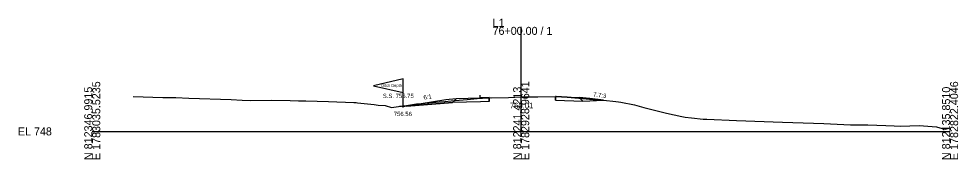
# Model space of a CAD drawing. Extents: x 5574 to 10203, y -10 to 9546.
# Drawn here: x 8574.3 to 8902.8, y 3990.3 to 4039.3 of the extents above; entities that cross this region are included whole.
import ezdxf

# ---------------------------------------------------------------- set-up
doc = ezdxf.new("R2010")
doc.units = 0
for name, color, linetype in [('Exist Cross Section Cell', 7, 'Continuous'), ('Exist XS Center Line Elevation Label', 7, 'Continuous'), ('Exist XS Ground Line', 7, 'Continuous'), ('Prop XS Ditch Slope Text', 7, 'Continuous'), ('Prop XS Ditch Standard Text', 7, 'Continuous'), ('Prop XS Dump Level', 7, 'Continuous'), ('Prop XS Earthwork Shape', 7, 'Continuous'), ('Prop XS EOT Tick Mark', 7, 'Continuous'), ('Prop XS Finish Grade', 7, 'Continuous'), ('Prop XS Finish Grade Earthwork', 7, 'Continuous'), ('Prop XS Finish Grade Paved Shoulder', 7, 'Continuous'), ('Prop XS Finish Grade Pavement', 7, 'Continuous'), ('Prop XS Hydro Typical Ditch Data', 7, 'Continuous'), ('Prop XS Pvmt Edge Slope', 7, 'Continuous'), ('Prop XS SS Elevation Text', 7, 'Continuous'), ('Prop XS Subgrade Earthwork', 7, 'Continuous'), ('Scratch_Level_3', 7, 'Continuous'), ('Scratch_Level_6', 7, 'Continuous')]:
    doc.layers.add(name, color=color, linetype=linetype)

msp = doc.modelspace()

# ---------------------------------------------------------------- linework, layer by layer
at = {"layer": 'Exist Cross Section Cell'}
for p, q in [((8750, 4000), (8750, 4036.49)), ((8600, 4000), (8750, 4000)), ((8750, 4000), (8900, 4000))]:
    msp.add_line(p, q, dxfattribs=at)
at = {"layer": 'Exist XS Ground Line'}
for p, q in [((8614.31, 4012.14), (8614.35, 4012.14)), ((8614.35, 4012.14), (8624.63, 4011.83)), ((8624.63, 4011.83), (8629.2, 4011.83)), ((8629.2, 4011.83), (8633.74, 4011.62)), ((8633.74, 4011.62), (8648.63, 4011.1)), ((8731.08, 4011.11), (8734.65, 4011.46)), ((8734.65, 4011.46), (8736.5, 4011.56)), ((8736.5, 4011.56), (8738.8, 4011.68)), ((8738.8, 4011.68), (8745.54, 4011.88)), ((8745.54, 4011.88), (8750, 4012.01)), ((8750, 4012.01), (8751.01, 4012.04)), ((8751.01, 4012.04), (8755.86, 4012.09)), ((8755.86, 4012.09), (8762.19, 4012.16)), ((8762.19, 4012.16), (8764.06, 4012.08)), ((8764.06, 4012.08), (8766.04, 4012)), ((8766.04, 4012), (8770.14, 4011.61)), ((8770.14, 4011.61), (8775.13, 4011.17)), ((8648.63, 4011.1), (8652.38, 4010.95)), ((8652.38, 4010.95), (8655.38, 4010.83)), ((8655.38, 4010.83), (8662.8, 4010.86)), ((8662.8, 4010.86), (8669.25, 4010.74)), ((8669.25, 4010.74), (8672.1, 4010.68)), ((8672.1, 4010.68), (8674.71, 4010.63)), ((8674.71, 4010.63), (8682.63, 4010.42)), ((8682.63, 4010.42), (8691.49, 4010.09)), ((8691.49, 4010.09), (8692.33, 4010.06)), ((8692.33, 4010.06), (8692.72, 4010.01)), ((8692.72, 4010.01), (8698.57, 4009.35)), ((8698.57, 4009.35), (8699.97, 4009.18)), ((8699.97, 4009.18), (8702.39, 4009.04)), ((8702.39, 4009.04), (8704.68, 4008.37)), ((8704.68, 4008.37), (8708.69, 4008.9)), ((8708.69, 4008.9), (8709.34, 4008.98)), ((8709.34, 4008.98), (8709.84, 4009.06)), ((8709.84, 4009.06), (8713.39, 4009.6)), ((8713.39, 4009.6), (8715.17, 4009.78)), ((8715.17, 4009.78), (8721.44, 4010.31)), ((8721.44, 4010.31), (8723.29, 4010.49)), ((8723.29, 4010.49), (8725.52, 4010.65)), ((8725.52, 4010.65), (8731.08, 4011.11)), ((8775.13, 4011.17), (8778.77, 4010.92)), ((8778.77, 4010.92), (8783.12, 4010.44)), ((8783.12, 4010.44), (8783.99, 4010.32)), ((8783.99, 4010.32), (8784.86, 4010.16)), ((8784.86, 4010.16), (8789.63, 4009.33)), ((8789.63, 4009.33), (8792.87, 4008.39)), ((8792.87, 4008.39), (8797.56, 4007.14)), ((8797.56, 4007.14), (8800.83, 4006.4)), ((8800.83, 4006.4), (8806.18, 4005.18)), ((8806.18, 4005.18), (8807.31, 4004.94)), ((8807.31, 4004.94), (8809.53, 4004.68)), ((8809.53, 4004.68), (8813.62, 4004.28)), ((8813.62, 4004.28), (8814.89, 4004.23)), ((8814.89, 4004.23), (8825.29, 4003.81)), ((8825.29, 4003.81), (8841.4, 4003.19)), ((8841.4, 4003.19), (8855.81, 4002.75)), ((8855.81, 4002.75), (8865.21, 4002.26)), ((8865.21, 4002.26), (8871.25, 4002.28)), ((8871.25, 4002.28), (8877.51, 4002.06)), ((8877.51, 4002.06), (8880.42, 4001.93)), ((8880.42, 4001.93), (8882.51, 4001.8)), ((8882.51, 4001.8), (8885.89, 4001.98)), ((8885.89, 4001.98), (8889.2, 4002.01)), ((8889.2, 4002.01), (8895.27, 4001.57)), ((8895.27, 4001.57), (8897.23, 4001.07)), ((8897.23, 4001.07), (8898.29, 4000.8)), ((8898.29, 4000.8), (8900, 4001.19))]:
    msp.add_line(p, q, dxfattribs=at)
at = {"layer": 'Prop XS Dump Level'}
for p, q in [((8708.7, 4018.34), (8698.4, 4015.94)), ((8708.7, 4013.54), (8708.7, 4018.34)), ((8698.4, 4015.94), (8708.7, 4013.54)), ((8708.7, 4008.34), (8708.7, 4013.54)), ((8738.81, 4011.79), (8735.7, 4011.73))]:
    msp.add_line(p, q, dxfattribs=at)
at = {"layer": 'Prop XS Earthwork Shape'}
for points in [[(8731.08, 4011.11), (8734.65, 4011.46), (8736.5, 4011.56), (8738.8, 4011.68), (8738.8, 4010.43), (8735.74, 4010.34), (8725.97, 4010.06), (8710.03, 4008.78), (8708.7, 4008.56), (8707.57, 4008.75), (8708.69, 4008.9), (8709.34, 4008.98), (8709.84, 4009.06), (8713.39, 4009.6), (8715.17, 4009.78), (8721.44, 4010.31), (8723.29, 4010.49), (8725.52, 4010.65)], [(8762, 4010.91), (8771.57, 4010.53), (8778.77, 4010.92), (8775.13, 4011.17), (8770.14, 4011.61), (8766.04, 4012), (8764.06, 4012.08), (8762.19, 4012.16), (8762, 4012.16)]]:
    msp.add_lwpolyline(points, close=True, dxfattribs=at)
at = {"layer": 'Prop XS EOT Tick Mark'}
msp.add_line((8735.7, 4011.59), (8735.7, 4012.59), dxfattribs=at)
at = {"layer": 'Prop XS Finish Grade'}
for p, q in [((8770.27, 4011.83), (8774, 4011.53)), ((8774, 4011.53), (8778.77, 4010.92)), ((8723.7, 4011.06), (8710.03, 4008.78)), ((8727.26, 4011.35), (8723.7, 4011.06))]:
    msp.add_line(p, q, dxfattribs=at)
at = {"layer": 'Prop XS Finish Grade Earthwork'}
for p, q in [((8708.7, 4008.56), (8707.57, 4008.75)), ((8710.03, 4008.78), (8708.7, 4008.56))]:
    msp.add_line(p, q, dxfattribs=at)
at = {"layer": 'Prop XS Finish Grade Paved Shoulder'}
msp.add_line((8735.7, 4011.59), (8727.26, 4011.35), dxfattribs=at)
at = {"layer": 'Prop XS Finish Grade Pavement'}
for p, q in [((8738.8, 4011.68), (8735.7, 4011.59)), ((8762, 4012.16), (8770.27, 4011.83))]:
    msp.add_line(p, q, dxfattribs=at)
at = {"layer": 'Prop XS Hydro Typical Ditch Data'}
msp.add_line((8708.7, 4008.56), (8707.57, 4008.75), dxfattribs=at)
at = {"layer": 'Prop XS Pvmt Edge Slope'}
for p, q in [((8770.27, 4011.83), (8771.57, 4010.53)), ((8727.26, 4011.35), (8725.97, 4010.06))]:
    msp.add_line(p, q, dxfattribs=at)
at = {"layer": 'Prop XS Subgrade Earthwork'}
for p, q in [((8738.8, 4010.43), (8738.8, 4011.68)), ((8762, 4010.91), (8762, 4012.16)), ((8725.97, 4010.06), (8710.03, 4008.78)), ((8735.74, 4010.34), (8725.97, 4010.06)), ((8738.8, 4010.43), (8735.74, 4010.34)), ((8762, 4010.91), (8771.57, 4010.53)), ((8771.57, 4010.53), (8778.77, 4010.92))]:
    msp.add_line(p, q, dxfattribs=at)
at = {"layer": 'Scratch_Level_3'}
for p, q in [((8774, 4011.53), (8770.27, 4011.83)), ((8770.27, 4011.83), (8771.57, 4010.53)), ((8778.77, 4010.92), (8774, 4011.53)), ((8723.7, 4011.06), (8710.03, 4008.78)), ((8710.03, 4008.78), (8725.97, 4010.06)), ((8727.26, 4011.35), (8723.7, 4011.06)), ((8725.97, 4010.06), (8727.26, 4011.35)), ((8771.57, 4010.53), (8778.77, 4010.92))]:
    msp.add_line(p, q, dxfattribs=at)
at = {"layer": 'Scratch_Level_6'}
for points in [[(8716.9, 4009.93), (8721.44, 4010.31), (8723.29, 4010.49), (8725.52, 4010.65), (8731.08, 4011.11), (8734.65, 4011.46), (8736.5, 4011.56), (8738.8, 4011.68), (8738.8, 4010.43), (8735.74, 4010.34), (8725.97, 4010.06), (8710.03, 4008.78)], [(8762, 4012.16), (8766.06, 4012), (8766.04, 4012), (8764.06, 4012.08), (8762.19, 4012.16)], [(8771.57, 4010.53), (8778.77, 4010.92), (8775.13, 4011.17), (8770.14, 4011.61), (8766.06, 4012), (8762, 4012.16), (8762, 4010.91)]]:
    msp.add_lwpolyline(points, close=True, dxfattribs=at)

# ---------------------------------------------------------------- texts
at = {"layer": 'Exist Cross Section Cell'}
for s, p in [('L1', (8740, 4036.49)), ('76+00.00 / 1', (8740, 4033.69)), ('EL 748', (8574, 3998.6))]:
    msp.add_text(s, height=2.8, dxfattribs=at).set_placement(p)
for s, p in [('N 812346.9915', (8600, 3990)), ('E 1783035.5235', (8602.8, 3990)), ('N 812241.4213', (8750, 3990)), ('E 1782928.9641', (8752.8, 3990)), ('N 812135.8510', (8900, 3990)), ('E 1782822.4046', (8902.8, 3990))]:
    msp.add_text(s, height=2.8, rotation=90, dxfattribs=at).set_placement(p)
at = {"layer": 'Exist XS Center Line Elevation Label'}
msp.add_text('760.01', height=2, dxfattribs=at).set_placement((8746.08, 4008.01))
at = {"layer": 'Prop XS Ditch Slope Text'}
for s, rotation, p in [('6:1', 9.4623, (8715.96, 4011.07)), ('7.7:3', 352.646, (8775.1, 4012.22))]:
    msp.add_text(s, height=1.5, rotation=rotation, dxfattribs=at).set_placement(p)
at = {"layer": 'Prop XS Ditch Standard Text'}
msp.add_text('756.56', height=1.5, dxfattribs=at).set_placement((8705.45, 4005.34))
at = {"layer": 'Prop XS Dump Level'}
for s, height, p in [('Ditch Depth', 1, (8701.05, 4015.51)), ('Eop', 0.3, (8738.8, 4011.38)), ('Case4', 0.04, (8723.7, 4010.8))]:
    msp.add_text(s, height=height, dxfattribs=at).set_placement(p)
at = {"layer": 'Prop XS SS Elevation Text'}
msp.add_text('S.S. 756.75', height=1.5, dxfattribs=at).set_placement((8701.61, 4011.65))

doc.saveas('drawing.dxf')
